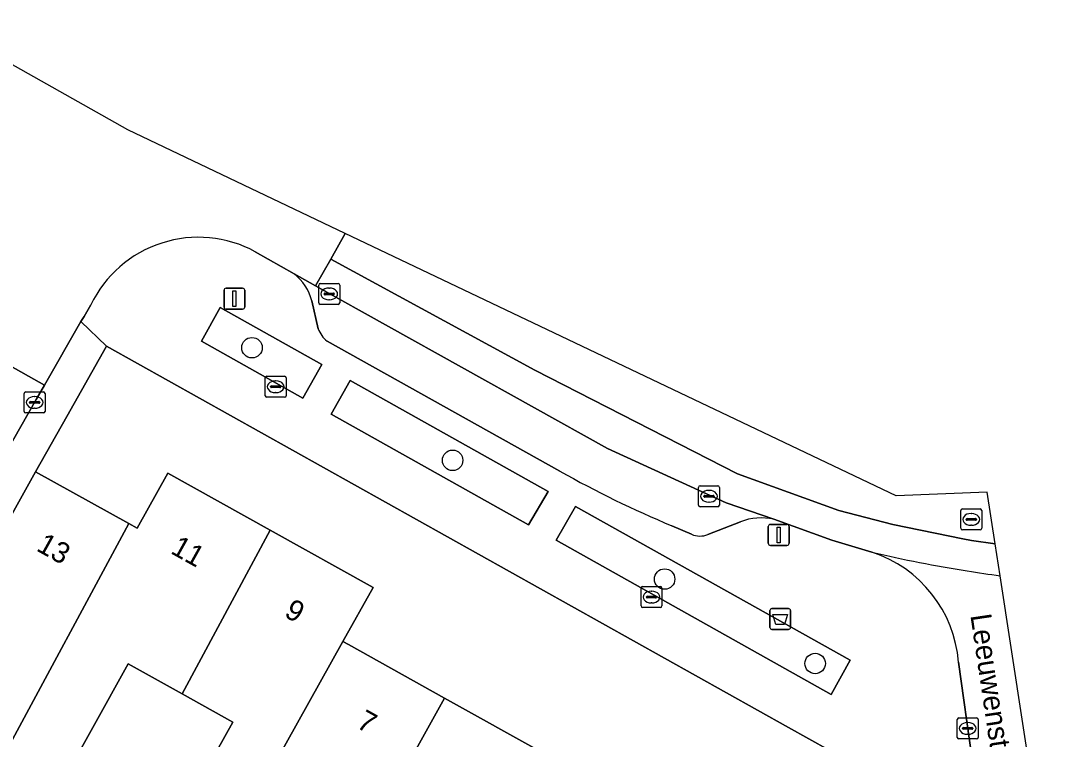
# Model space of a CAD drawing. Extents: x 163147 to 163550, y 380933 to 381639.
# Drawn here: x 163413.52 to 163463.07, y 381516.74 to 381551.11 of the extents above; entities that cross this region are included whole.
import ezdxf

# ---------------------------------------------------------------- set-up
doc = ezdxf.new("R2010")
doc.units = 0
for name, color, linetype in [('IMGEO_Afvalbak', 7, 'Continuous'), ('IMGEO_Boom', 7, 'Continuous'), ('IMGEO_Erf', 7, 'Continuous'), ('IMGEO_Groenvoorziening', 7, 'Continuous'), ('IMGEO_Kolk', 7, 'Continuous'), ('IMGEO_Lichtmast', 7, 'Continuous'), ('IMGEO_Openbare_ruimte_label', 7, 'Continuous'), ('IMGEO_Pand', 7, 'Continuous'), ('IMGEO_Pand_nummerreeks', 7, 'Continuous'), ('IMGEO_Parkeervlak_open', 7, 'Continuous'), ('IMGEO_Rijbaan_lokaal_gesloten', 7, 'Continuous'), ('IMGEO_Rijbaan_lokaal_open', 7, 'Continuous'), ('IMGEO_Rioolput', 7, 'Continuous'), ('IMGEO_Voetpad_open', 7, 'Continuous')]:
    doc.layers.add(name, color=color, linetype=linetype)

msp = doc.modelspace()

# ---------------------------------------------------------------- linework, layer by layer
at = {"layer": 'IMGEO_Afvalbak'}
for p, q in [((163449.331, 381522.094), (163449.331, 381522.894)), ((163449.331, 381522.894), (163449.331, 381522.094)), ((163449.431, 381522.994), (163450.221, 381522.994)), ((163450.221, 381522.994), (163449.431, 381522.994)), ((163450.321, 381522.894), (163450.321, 381522.094)), ((163450.321, 381522.094), (163450.321, 381522.894)), ((163450.221, 381521.994), (163449.431, 381521.994)), ((163449.431, 381521.994), (163450.221, 381521.994))]:
    msp.add_line(p, q, dxfattribs=at)
msp.add_lwpolyline([(163449.474, 381522.708), (163450.178, 381522.708), (163450.029, 381522.238), (163449.623, 381522.238), (163449.474, 381522.708)], dxfattribs=at)
for centre, start, end in [((163449.431, 381522.894), 90, 180), ((163449.431, 381522.894), 90, 180), ((163450.221, 381522.894), 0, 90), ((163450.221, 381522.894), 360, 90), ((163449.431, 381522.094), 180, 270), ((163449.431, 381522.094), 180, 270), ((163450.221, 381522.094), 270, 0), ((163450.221, 381522.094), 270, 0)]:
    msp.add_arc(centre, 0.1, start, end, dxfattribs=at)
at = {"layer": 'IMGEO_Boom'}
for centre in [(163424.573, 381535.469), (163434.164, 381530.083), (163444.299, 381524.403), (163451.494, 381520.366)]:
    msp.add_circle(centre, 0.489, dxfattribs=at)
at = {"layer": 'IMGEO_Erf'}
for points in [[(163454.104, 381515.141), (163450.218, 381517.299), (163417.612, 381535.547), (163415.715, 381532.175), (163414.231, 381529.537), (163418.679, 381527.058), (163419.083, 381526.833), (163420.55, 381529.464), (163425.443, 381526.737), (163430.362, 381523.995), (163428.924, 381521.416), (163429.18, 381521.273), (163433.784, 381518.707), (163438.623, 381516.009)], [(163421.668, 381513.995), (163423.654, 381517.558), (163421.229, 381518.91), (163418.659, 381520.343), (163415.352, 381514.411)]]:
    msp.add_lwpolyline(points, dxfattribs=at)
at = {"layer": 'IMGEO_Groenvoorziening'}
for points in [[(163423.052, 381537.386), (163422.159, 381535.779), (163427.004, 381533.059), (163427.905, 381534.663)], [(163429.268, 381533.898), (163428.366, 381532.293), (163437.794, 381526.999), (163438.731, 381528.588)], [(163440.035, 381527.876), (163439.112, 381526.269), (163452.265, 381518.889), (163453.162, 381520.518)]]:
    msp.add_lwpolyline(points, close=True, dxfattribs=at)
at = {"layer": 'IMGEO_Kolk'}
for p, q in [((163427.765, 381537.616), (163427.765, 381538.468)), ((163427.84, 381538.542), (163428.692, 381538.542)), ((163428.253, 381538.322), (163428.278, 381538.322)), ((163428.766, 381538.468), (163428.766, 381537.616)), ((163428.024, 381538.036), (163428.024, 381538.048)), ((163428.462, 381537.999), (163428.064, 381537.999)), ((163428.067, 381538.085), (163428.465, 381538.085)), ((163428.276, 381537.762), (163428.251, 381537.762)), ((163428.508, 381538.048), (163428.508, 381538.036)), ((163428.692, 381537.542), (163427.84, 381537.542)), ((163425.205, 381533.175), (163425.205, 381534.027)), ((163425.28, 381534.101), (163426.132, 381534.101)), ((163425.693, 381533.881), (163425.718, 381533.881)), ((163426.206, 381534.027), (163426.206, 381533.175)), ((163413.683, 381532.426), (163413.683, 381533.278)), ((163413.758, 381533.352), (163414.61, 381533.352)), ((163414.684, 381533.278), (163414.684, 381532.426)), ((163425.464, 381533.595), (163425.464, 381533.607)), ((163425.902, 381533.558), (163425.504, 381533.558)), ((163425.507, 381533.644), (163425.905, 381533.644)), ((163425.716, 381533.321), (163425.691, 381533.321)), ((163425.948, 381533.607), (163425.948, 381533.595)), ((163413.942, 381532.846), (163413.942, 381532.858)), ((163414.38, 381532.809), (163413.982, 381532.809)), ((163413.985, 381532.895), (163414.383, 381532.895)), ((163414.171, 381533.132), (163414.196, 381533.132)), ((163414.426, 381532.858), (163414.426, 381532.846)), ((163426.132, 381533.101), (163425.28, 381533.101)), ((163414.61, 381532.352), (163413.758, 381532.352)), ((163414.194, 381532.572), (163414.169, 381532.572)), ((163445.994, 381528.864), (163446.846, 381528.864)), ((163445.919, 381527.938), (163445.919, 381528.79)), ((163446.178, 381528.358), (163446.178, 381528.37)), ((163446.616, 381528.321), (163446.218, 381528.321)), ((163446.221, 381528.407), (163446.619, 381528.407)), ((163446.407, 381528.644), (163446.432, 381528.644)), ((163446.662, 381528.37), (163446.662, 381528.358)), ((163446.92, 381528.79), (163446.92, 381527.938)), ((163446.846, 381527.864), (163445.994, 381527.864)), ((163446.43, 381528.084), (163446.405, 381528.084)), ((163443.171, 381523.118), (163443.171, 381523.97)), ((163443.246, 381524.044), (163444.098, 381524.044)), ((163444.172, 381523.97), (163444.172, 381523.118)), ((163443.43, 381523.538), (163443.43, 381523.55)), ((163443.868, 381523.501), (163443.47, 381523.501)), ((163443.473, 381523.587), (163443.871, 381523.587)), ((163443.659, 381523.824), (163443.684, 381523.824)), ((163443.914, 381523.55), (163443.914, 381523.538)), ((163444.098, 381523.044), (163443.246, 381523.044)), ((163443.682, 381523.264), (163443.657, 381523.264)), ((163458.285, 381516.834), (163458.285, 381517.686)), ((163458.36, 381517.76), (163459.212, 381517.76)), ((163458.773, 381517.54), (163458.798, 381517.54)), ((163459.286, 381517.686), (163459.286, 381516.834)), ((163458.544, 381517.254), (163458.544, 381517.266)), ((163458.982, 381517.217), (163458.584, 381517.217)), ((163458.587, 381517.303), (163458.985, 381517.303)), ((163458.796, 381516.98), (163458.771, 381516.98)), ((163459.028, 381517.266), (163459.028, 381517.254)), ((163459.212, 381516.76), (163458.36, 381516.76))]:
    msp.add_line(p, q, dxfattribs=at)
for points in [[(163427.765, 381537.616), (163427.765, 381538.468)], [(163427.84, 381538.542), (163428.692, 381538.542)], [(163428.766, 381538.468), (163428.766, 381537.616)], [(163428.692, 381537.542), (163427.84, 381537.542)], [(163425.205, 381533.175), (163425.205, 381534.027)], [(163425.28, 381534.101), (163426.132, 381534.101)], [(163426.206, 381534.027), (163426.206, 381533.175)], [(163413.683, 381532.426), (163413.683, 381533.278)], [(163413.758, 381533.352), (163414.61, 381533.352)], [(163414.684, 381533.278), (163414.684, 381532.426)], [(163426.132, 381533.101), (163425.28, 381533.101)], [(163414.61, 381532.352), (163413.758, 381532.352)], [(163445.994, 381528.864), (163446.846, 381528.864)], [(163445.919, 381527.938), (163445.919, 381528.79)], [(163446.92, 381528.79), (163446.92, 381527.938)], [(163446.846, 381527.864), (163445.994, 381527.864)], [(163443.171, 381523.118), (163443.171, 381523.97)], [(163443.246, 381524.044), (163444.098, 381524.044)], [(163444.172, 381523.97), (163444.172, 381523.118)], [(163444.098, 381523.044), (163443.246, 381523.044)], [(163458.285, 381516.834), (163458.285, 381517.686)], [(163458.36, 381517.76), (163459.212, 381517.76)], [(163459.286, 381517.686), (163459.286, 381516.834)], [(163459.212, 381516.76), (163458.36, 381516.76)]]:
    msp.add_lwpolyline(points, dxfattribs=at)
for centre, radius, start, end in [((163427.842, 381538.466), 0.0765, 91.552, 178.448), ((163427.842, 381538.466), 0.0765, 91.552, 178.448), ((163428.69, 381538.466), 0.0765, 1.552, 88.448), ((163428.69, 381538.466), 0.0765, 1.552, 88.448), ((163428.064, 381538.045), 0.0403, 85.8775, 175.7526), ((163428.061, 381538.035), 0.0366, 178.938, 274.7102), ((163428.465, 381538.042), 0.043, 264.8664, 352.4533), ((163428.469, 381538.047), 0.0386, 1.7309, 96.639), ((163427.842, 381537.618), 0.0765, 181.552, 268.448), ((163427.842, 381537.618), 0.0765, 181.552, 268.448), ((163428.69, 381537.618), 0.0765, 271.552, 358.448), ((163428.69, 381537.618), 0.0765, 271.552, 358.448), ((163425.282, 381534.025), 0.0765, 91.552, 178.448), ((163425.282, 381534.025), 0.0765, 91.552, 178.448), ((163426.13, 381534.025), 0.0765, 1.552, 88.448), ((163426.13, 381534.025), 0.0765, 1.552, 88.448), ((163413.76, 381533.276), 0.0765, 91.552, 178.448), ((163413.76, 381533.276), 0.0765, 91.552, 178.448), ((163414.608, 381533.276), 0.0765, 1.552, 88.448), ((163414.608, 381533.276), 0.0765, 1.552, 88.448), ((163425.504, 381533.604), 0.0403, 85.8775, 175.7526), ((163425.501, 381533.594), 0.0366, 178.938, 274.7102), ((163425.905, 381533.601), 0.043, 264.8664, 352.4533), ((163425.909, 381533.606), 0.0386, 1.7309, 96.639), ((163413.982, 381532.855), 0.0403, 85.8775, 175.7526), ((163413.979, 381532.845), 0.0366, 178.938, 274.7102), ((163414.383, 381532.852), 0.043, 264.8664, 352.4533), ((163414.387, 381532.857), 0.0386, 1.7309, 96.639), ((163425.282, 381533.177), 0.0765, 181.552, 268.448), ((163425.282, 381533.177), 0.0765, 181.552, 268.448), ((163426.13, 381533.177), 0.0765, 271.552, 358.448), ((163426.13, 381533.177), 0.0765, 271.552, 358.448), ((163413.76, 381532.428), 0.0765, 181.552, 268.448), ((163413.76, 381532.428), 0.0765, 181.552, 268.448), ((163414.608, 381532.428), 0.0765, 271.552, 358.448), ((163414.608, 381532.428), 0.0765, 271.552, 358.448), ((163445.996, 381528.788), 0.0765, 91.552, 178.448), ((163445.996, 381528.788), 0.0765, 91.552, 178.448), ((163446.844, 381528.788), 0.0765, 1.552, 88.448), ((163446.844, 381528.788), 0.0765, 1.552, 88.448), ((163446.218, 381528.367), 0.0403, 85.8775, 175.7526), ((163446.215, 381528.357), 0.0366, 178.938, 274.7102), ((163446.619, 381528.364), 0.043, 264.8664, 352.4533), ((163446.623, 381528.369), 0.0386, 1.7309, 96.639), ((163445.996, 381527.94), 0.0765, 181.552, 268.448), ((163445.996, 381527.94), 0.0765, 181.552, 268.448), ((163446.844, 381527.94), 0.0765, 271.552, 358.448), ((163446.844, 381527.94), 0.0765, 271.552, 358.448), ((163443.248, 381523.968), 0.0765, 91.552, 178.448), ((163443.248, 381523.968), 0.0765, 91.552, 178.448), ((163444.096, 381523.968), 0.0765, 1.552, 88.448), ((163444.096, 381523.968), 0.0765, 1.552, 88.448), ((163443.47, 381523.547), 0.0403, 85.8775, 175.7526), ((163443.467, 381523.537), 0.0366, 178.938, 274.7102), ((163443.871, 381523.544), 0.043, 264.8664, 352.4533), ((163443.875, 381523.549), 0.0386, 1.7309, 96.639), ((163443.248, 381523.12), 0.0765, 181.552, 268.448), ((163443.248, 381523.12), 0.0765, 181.552, 268.448), ((163444.096, 381523.12), 0.0765, 271.552, 358.448), ((163444.096, 381523.12), 0.0765, 271.552, 358.448), ((163458.362, 381517.684), 0.0765, 91.552, 178.448), ((163458.362, 381517.684), 0.0765, 91.552, 178.448), ((163459.21, 381517.684), 0.0765, 1.552, 88.448), ((163459.21, 381517.684), 0.0765, 1.552, 88.448), ((163458.584, 381517.263), 0.0403, 85.8775, 175.7526), ((163458.581, 381517.253), 0.0366, 178.938, 274.7102), ((163458.985, 381517.26), 0.043, 264.8664, 352.4533), ((163458.989, 381517.265), 0.0386, 1.7309, 96.639), ((163458.362, 381516.836), 0.0765, 181.552, 268.448), ((163458.362, 381516.836), 0.0765, 181.552, 268.448), ((163459.21, 381516.836), 0.0765, 271.552, 358.448), ((163459.21, 381516.836), 0.0765, 271.552, 358.448)]:
    msp.add_arc(centre, radius, start, end, dxfattribs=at)
for centre, major_axis, ratio, start_param, end_param in [((163428.252, 381538.042), (-0.387, 0.002), 0.722429, 4.712389, 7.853982), ((163428.277, 381538.042), (-0.39, 0.002), 0.717154, 1.570796, 4.712389), ((163425.692, 381533.601), (-0.387, 0.002), 0.722429, 4.712389, 7.853982), ((163425.717, 381533.601), (-0.39, 0.002), 0.717154, 1.570796, 4.712389), ((163414.17, 381532.852), (-0.387, 0.002), 0.722429, 4.712389, 7.853982), ((163414.195, 381532.852), (-0.39, 0.002), 0.717154, 1.570796, 4.712389), ((163446.406, 381528.364), (-0.387, 0.002), 0.722429, 4.712389, 7.853982), ((163446.431, 381528.364), (-0.39, 0.002), 0.717154, 1.570796, 4.712389), ((163443.658, 381523.544), (-0.387, 0.002), 0.722429, 4.712389, 7.853982), ((163443.683, 381523.544), (-0.39, 0.002), 0.717154, 1.570796, 4.712389), ((163458.772, 381517.26), (-0.387, 0.002), 0.722429, 4.712389, 7.853982), ((163458.797, 381517.26), (-0.39, 0.002), 0.717154, 1.570796, 4.712389)]:
    msp.add_ellipse(centre, major_axis=major_axis, ratio=ratio, start_param=start_param, end_param=end_param, dxfattribs=at)
at = {"layer": 'IMGEO_Lichtmast'}
for p, q in [((163423.337, 381538.314), (163424.127, 381538.314)), ((163424.127, 381538.314), (163423.337, 381538.314)), ((163423.237, 381537.414), (163423.237, 381538.214)), ((163423.237, 381538.214), (163423.237, 381537.414)), ((163424.227, 381538.214), (163424.227, 381537.414)), ((163424.227, 381537.414), (163424.227, 381538.214)), ((163424.127, 381537.314), (163423.337, 381537.314)), ((163423.337, 381537.314), (163424.127, 381537.314)), ((163449.256, 381526.114), (163449.256, 381526.914)), ((163449.256, 381526.914), (163449.256, 381526.114)), ((163449.356, 381527.014), (163450.146, 381527.014)), ((163450.146, 381527.014), (163449.356, 381527.014)), ((163450.246, 381526.914), (163450.246, 381526.114)), ((163450.246, 381526.114), (163450.246, 381526.914)), ((163450.146, 381526.014), (163449.356, 381526.014)), ((163449.356, 381526.014), (163450.146, 381526.014))]:
    msp.add_line(p, q, dxfattribs=at)
for points in [[(163423.657, 381538.189), (163423.807, 381538.189), (163423.807, 381537.439), (163423.657, 381537.439), (163423.657, 381538.189)], [(163449.676, 381526.889), (163449.826, 381526.889), (163449.826, 381526.139), (163449.676, 381526.139), (163449.676, 381526.889)]]:
    msp.add_lwpolyline(points, dxfattribs=at)
for centre, start, end in [((163423.337, 381538.214), 90, 180), ((163423.337, 381538.214), 90, 180), ((163424.127, 381538.214), 0, 90), ((163424.127, 381538.214), 360, 90), ((163423.337, 381537.414), 180, 270), ((163423.337, 381537.414), 180, 270), ((163424.127, 381537.414), 270, 0), ((163424.127, 381537.414), 270, 0), ((163449.356, 381526.914), 90, 180), ((163449.356, 381526.914), 90, 180), ((163450.146, 381526.914), 0, 90), ((163450.146, 381526.914), 360, 90), ((163449.356, 381526.114), 180, 270), ((163449.356, 381526.114), 180, 270), ((163450.146, 381526.114), 270, 0), ((163450.146, 381526.114), 270, 0)]:
    msp.add_arc(centre, 0.1, start, end, dxfattribs=at)
at = {"layer": 'IMGEO_Pand'}
for points in [[(163412.675, 381515.904), (163418.679, 381527.058), (163414.231, 381529.537), (163410.272, 381522.434), (163412.7, 381521.08), (163410.492, 381517.121)], [(163418.679, 381527.058), (163412.675, 381515.904), (163414.86, 381514.686), (163415.352, 381514.411), (163418.659, 381520.343), (163421.229, 381518.91), (163425.443, 381526.737), (163420.55, 381529.464), (163419.083, 381526.833)], [(163428.924, 381521.416), (163430.362, 381523.995), (163425.443, 381526.737), (163421.229, 381518.91), (163423.654, 381517.558), (163421.668, 381513.995), (163424.046, 381512.669)], [(163433.784, 381518.707), (163429.18, 381521.273), (163428.924, 381521.416), (163424.046, 381512.669), (163422.735, 381510.317), (163425.248, 381508.916), (163427.438, 381512.846), (163429.786, 381511.537)], [(163438.623, 381516.009), (163433.784, 381518.707), (163429.786, 381511.537), (163432.238, 381510.17), (163430.051, 381506.247), (163432.602, 381504.825)]]:
    msp.add_lwpolyline(points, close=True, dxfattribs=at)
at = {"layer": 'IMGEO_Parkeervlak_open'}
for points in [[(163427.603, 381538.428), (163426.583, 381538.996)], [(163449.519, 381527.266), (163447.245, 381528.043), (163441.574, 381530.652), (163427.603, 381538.428)], [(163427.433, 381537.711), (163427.739, 381536.373)], [(163428.16, 381535.78), (163439.29, 381529.567)], [(163444.637, 381526.953), (163445.586, 381526.544)], [(163446.361, 381526.531), (163447.925, 381527.142)]]:
    msp.add_lwpolyline(points, dxfattribs=at)
for centre, radius, start, end in [((163425.208, 381537.163), 2.292, 13.8403, 53.1273), ((163429.04, 381536.851), 1.386, 200.1645, 230.5812), ((163464.302, 381573.954), 50.949, 240.5988, 247.2958), ((163448.929, 381524.548), 2.782, 77.7465, 111.1499), ((163445.989, 381527.481), 1.02, 246.7026, 291.3754)]:
    msp.add_arc(centre, radius, start, end, dxfattribs=at)
at = {"layer": 'IMGEO_Rijbaan_lokaal_gesloten'}
msp.add_lwpolyline([(163460.104, 381526.095), (163459.725, 381528.559), (163455.374, 381528.381), (163429.034, 381540.936), (163428.342, 381539.709), (163438.087, 381534.395), (163447.781, 381529.443), (163452.628, 381527.689), (163455.206, 381527.019), (163458.555, 381526.33), (163458.97, 381526.245)], close=True, dxfattribs=at)
for points in [[(163460.104, 381526.095), (163458.97, 381526.245), (163458.555, 381526.33), (163455.206, 381527.019), (163452.628, 381527.689), (163447.781, 381529.443), (163438.087, 381534.395), (163428.342, 381539.709), (163427.603, 381538.428), (163441.574, 381530.652), (163447.245, 381528.043), (163449.519, 381527.266), (163452.292, 381526.26), (163454.211, 381525.686)], [(163460.339, 381524.563), (163460.104, 381526.095)]]:
    msp.add_lwpolyline(points, dxfattribs=at)
for centre, radius, start, end in [((163468.59, 381586.897), 62.877, 256.78041, 261.01124), ((163468.685, 381587.432), 63.42, 261.00199, 262.43797)]:
    msp.add_arc(centre, radius, start, end, dxfattribs=at)
at = {"layer": 'IMGEO_Rijbaan_lokaal_open'}
for points in [[(163424.732, 381540.058), (163426.583, 381538.996), (163427.603, 381538.428), (163428.342, 381539.709), (163429.034, 381540.936), (163418.634, 381545.893), (163409.378, 381551.108)], [(163412.47, 381539.47), (163410.599, 381535.956), (163414.654, 381533.678), (163416.384, 381536.72), (163416.546, 381536.957), (163416.871, 381537.519)], [(163463.069, 381506.793), (163460.339, 381524.563)], [(163458.348, 381520.437), (163458.993, 381515.776), (163459.158, 381514.585), (163459.618, 381511.259), (163460.288, 381506.424), (163461.268, 381506.554), (163463.069, 381506.793)]]:
    msp.add_lwpolyline(points, dxfattribs=at)
msp.add_lwpolyline([(163414.262, 381532.989), (163414.654, 381533.678), (163410.599, 381535.956), (163409.219, 381533.373), (163408.677, 381532.42), (163400.477, 381518.009), (163399.217, 381515.793), (163392.697, 381504.335), (163396.678, 381502.07), (163399.031, 381506.208), (163400.059, 381508.016), (163402.013, 381511.452), (163403.04, 381513.257)], close=True, dxfattribs=at)
for centre, radius, start, end in [((163422.009, 381535.048), 5.702, 61.4772, 154.3223), ((163468.59, 381586.897), 62.877, 256.78041, 261.01124), ((163452.349, 381519.964), 6.017, 4.5085, 71.9783), ((163468.685, 381587.432), 63.42, 261.00199, 262.43797)]:
    msp.add_arc(centre, radius, start, end, dxfattribs=at)
at = {"layer": 'IMGEO_Rioolput'}
for p, q in [((163458.458, 381526.831), (163458.458, 381527.683)), ((163458.533, 381527.757), (163459.385, 381527.757)), ((163458.946, 381527.537), (163458.971, 381527.537)), ((163459.459, 381527.683), (163459.459, 381526.831)), ((163458.717, 381527.251), (163458.717, 381527.263)), ((163459.155, 381527.214), (163458.757, 381527.214)), ((163458.76, 381527.3), (163459.158, 381527.3)), ((163458.969, 381526.977), (163458.944, 381526.977)), ((163459.201, 381527.263), (163459.201, 381527.251)), ((163459.385, 381526.757), (163458.533, 381526.757))]:
    msp.add_line(p, q, dxfattribs=at)
for points in [[(163458.458, 381526.831), (163458.458, 381527.683)], [(163458.533, 381527.757), (163459.385, 381527.757)], [(163459.459, 381527.683), (163459.459, 381526.831)], [(163459.385, 381526.757), (163458.533, 381526.757)]]:
    msp.add_lwpolyline(points, dxfattribs=at)
for centre, radius, start, end in [((163458.535, 381527.681), 0.0765, 91.552, 178.448), ((163458.535, 381527.681), 0.0765, 91.552, 178.448), ((163459.383, 381527.681), 0.0765, 1.552, 88.448), ((163459.383, 381527.681), 0.0765, 1.552, 88.448), ((163458.535, 381526.833), 0.0765, 181.552, 268.448), ((163458.535, 381526.833), 0.0765, 181.552, 268.448), ((163458.757, 381527.26), 0.0403, 85.8775, 175.7526), ((163458.754, 381527.25), 0.0366, 178.938, 274.7102), ((163459.158, 381527.257), 0.043, 264.8664, 352.4533), ((163459.162, 381527.262), 0.0386, 1.7309, 96.639), ((163459.383, 381526.833), 0.0765, 271.552, 358.448), ((163459.383, 381526.833), 0.0765, 271.552, 358.448)]:
    msp.add_arc(centre, radius, start, end, dxfattribs=at)
for centre, major_axis, ratio, start_param, end_param in [((163458.945, 381527.257), (-0.387, 0.002), 0.722429, 4.712389, 7.853982), ((163458.97, 381527.257), (-0.39, 0.002), 0.717154, 1.570796, 4.712389)]:
    msp.add_ellipse(centre, major_axis=major_axis, ratio=ratio, start_param=start_param, end_param=end_param, dxfattribs=at)
at = {"layer": 'IMGEO_Voetpad_open'}
for points in [[(163426.583, 381538.996), (163424.732, 381540.058)], [(163416.871, 381537.519), (163416.546, 381536.957), (163416.384, 381536.72), (163417.612, 381535.547), (163450.218, 381517.299), (163454.104, 381515.141), (163455.892, 381514.188), (163459.158, 381514.585), (163458.993, 381515.776), (163458.348, 381520.437)], [(163427.739, 381536.373), (163427.433, 381537.711)], [(163414.231, 381529.537), (163415.715, 381532.175), (163417.612, 381535.547), (163416.384, 381536.72), (163414.654, 381533.678), (163414.262, 381532.989), (163403.04, 381513.257), (163402.013, 381511.452), (163400.059, 381508.016), (163399.031, 381506.208), (163396.678, 381502.07), (163395.5, 381500)], [(163439.29, 381529.567), (163428.16, 381535.78)], [(163393.804, 381490.754), (163396.932, 381490.11), (163399.443, 381490.376), (163402.139, 381490.739), (163401.915, 381492.238), (163401.169, 381497.642), (163400.844, 381500), (163400.424, 381503.043), (163400.279, 381504.213), (163400.246, 381504.532), (163404.666, 381512.456), (163405.156, 381513.335), (163410.272, 381522.434), (163414.231, 381529.537)], [(163445.586, 381526.544), (163444.637, 381526.953)], [(163447.925, 381527.142), (163446.361, 381526.531)], [(163454.211, 381525.686), (163452.292, 381526.26), (163449.519, 381527.266)]]:
    msp.add_lwpolyline(points, dxfattribs=at)
for points in [[(163427.004, 381533.059), (163422.159, 381535.779), (163423.052, 381537.386), (163427.905, 381534.663)], [(163437.794, 381526.999), (163428.366, 381532.293), (163429.268, 381533.898), (163438.731, 381528.588)], [(163452.265, 381518.889), (163439.112, 381526.269), (163440.035, 381527.876), (163453.162, 381520.518)]]:
    msp.add_lwpolyline(points, close=True, dxfattribs=at)
for centre, radius, start, end in [((163422.009, 381535.048), 5.702, 61.4772, 154.3223), ((163425.208, 381537.163), 2.292, 13.8403, 53.1273), ((163429.04, 381536.851), 1.386, 200.1645, 230.5812), ((163464.302, 381573.954), 50.949, 240.5988, 247.2958), ((163448.929, 381524.548), 2.782, 77.7465, 111.1499), ((163445.989, 381527.481), 1.02, 246.7026, 291.3754), ((163452.349, 381519.964), 6.017, 4.5085, 71.9783)]:
    msp.add_arc(centre, radius, start, end, dxfattribs=at)

# ---------------------------------------------------------------- texts
at = {"layer": 'IMGEO_Openbare_ruimte_label'}
msp.add_text('Leeuwenstraat', height=1, rotation=278.4543, dxfattribs=at).set_placement((163458.913, 381522.671))
at = {"layer": 'IMGEO_Pand_nummerreeks'}
for s, rotation, p in [('13', 330.8678, (163414.216, 381525.79)), ('11', 330.8676, (163420.635, 381525.662)), ('9', 330.8651, (163426.065, 381522.636)), ('7', 330.8651, (163429.516, 381517.331))]:
    msp.add_text(s, height=1, rotation=rotation, dxfattribs=at).set_placement(p)

doc.saveas('drawing.dxf')
